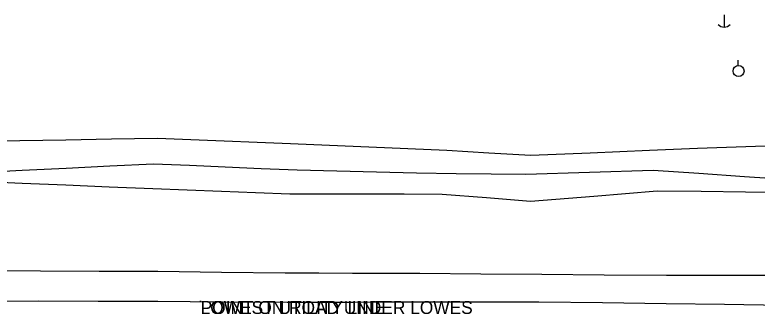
# Model space of a CAD drawing. Extents: x 1939239 to 1943096, y 531224 to 537447.
# Drawn here: x 1940013.5 to 1940300.4, y 534763.5 to 534879.2 of the extents above; entities that cross this region are included whole.
import ezdxf

# ---------------------------------------------------------------- set-up
doc = ezdxf.new("R2010")
doc.units = 0
for name, color, linetype in [('S_DITCHLINE', 7, 'Continuous'), ('S_EDGE_PAVEMENT', 7, 'Continuous'), ('S_ELECTRIC_UTILITIES_ANNOT', 7, 'Continuous'), ('S_MSC_PT_SYM', 7, 'Continuous'), ('S_PAVEMENT_CROWN', 7, 'Continuous'), ('S_SURVEY_TEXT_ANNOT', 7, 'Continuous'), ('S_UTILITY_POLE', 7, 'Continuous'), ('S_UTL_PT_SYM', 7, 'Continuous')]:
    doc.layers.add(name, color=color, linetype=linetype)

msp = doc.modelspace()

# ---------------------------------------------------------------- linework, layer by layer
at = {"layer": 'S_DITCHLINE'}
for points in [[(1940314.63, 534828.78), (1940295.99, 534828.12), (1940277.35, 534827.45), (1940258.7, 534826.78), (1940235.79, 534825.77), (1940212.88, 534824.76), (1940196.66, 534825.76), (1940180.44, 534826.76), (1940165.34, 534827.39), (1940150.24, 534828.03), (1940135.14, 534828.66), (1940120.04, 534829.3), (1940107.19, 534829.82), (1940094.33, 534830.34), (1940081.48, 534830.86), (1940068.62, 534831.38), (1940050.9, 534831.06), (1940033.18, 534830.75), (1940015.45, 534830.44), (1939997.73, 534830.12)], [(1940313.14, 534815.42), (1940295.47, 534816.61), (1940277.8, 534817.81), (1940260.13, 534819), (1940235.57, 534818.24), (1940211, 534817.49), (1940197.54, 534817.57), (1940184.07, 534817.66), (1940168.68, 534818.02), (1940153.3, 534818.39), (1940137.91, 534818.76), (1940122.53, 534819.13), (1940108.66, 534819.71), (1940094.8, 534820.3), (1940080.93, 534820.88), (1940067.06, 534821.47), (1940050.16, 534820.64), (1940033.26, 534819.81), (1940016.36, 534818.98), (1939999.46, 534818.15)], [(1940313, 534810.48), (1940295.89, 534810.66), (1940278.78, 534810.84), (1940261.66, 534811.02), (1940237.23, 534809.01), (1940212.79, 534807.01), (1940195.74, 534808.4), (1940178.69, 534809.79), (1940163.96, 534809.8), (1940149.23, 534809.8), (1940134.5, 534809.8), (1940119.78, 534809.8), (1940106.54, 534810.32), (1940093.3, 534810.84), (1940080.06, 534811.35), (1940066.82, 534811.87), (1940049.99, 534812.58), (1940033.16, 534813.3), (1940016.33, 534814.01), (1939999.5, 534814.73)]]:
    msp.add_lwpolyline(points, dxfattribs=at)
at = {"layer": 'S_EDGE_PAVEMENT'}
msp.add_lwpolyline([(1939852.77, 534782.14), (1939874.25, 534781.93), (1939896.9, 534781.77), (1939919.55, 534781.6), (1939942.13, 534781.22), (1939964.7, 534780.83), (1939979.38, 534780.67), (1939994.06, 534780.51), (1940008.74, 534780.35), (1940023.42, 534780.18), (1940046.09, 534780.11), (1940068.75, 534780.04), (1940093.37, 534779.74), (1940118, 534779.43), (1940130.99, 534779.4), (1940143.99, 534779.36), (1940156.99, 534779.33), (1940169.99, 534779.3), (1940193.57, 534779.1), (1940217.16, 534778.91), (1940241.23, 534778.7), (1940265.3, 534778.5), (1940288.18, 534778.5), (1940311.06, 534778.51)], dxfattribs=at)
at = {"layer": 'S_MSC_PT_SYM'}
msp.add_lwpolyline([(1940085.29, 534768.53), (1940085.29, 534768.58), (1940085.29, 534768.53), (1940085.24, 534768.53), (1940085.29, 534768.53), (1940085.29, 534768.48), (1940085.29, 534768.53), (1940085.34, 534768.53)], dxfattribs=at)
at = {"layer": 'S_PAVEMENT_CROWN'}
msp.add_lwpolyline([(1939852.31, 534771.21), (1939874.42, 534771.08), (1939896.28, 534770.35), (1939918.14, 534769.62), (1939939.65, 534769.35), (1939961.17, 534769.08), (1939985.43, 534768.78), (1940009.68, 534768.48), (1940022.61, 534768.64), (1940045.69, 534768.54), (1940068.77, 534768.44), (1940093.77, 534768.28), (1940118.76, 534768.12), (1940131.55, 534768.14), (1940144.34, 534768.16), (1940157.13, 534768.18), (1940169.93, 534768.2), (1940192.98, 534768.23), (1940216.04, 534768.26), (1940240.59, 534767.93), (1940265.13, 534767.61), (1940287.69, 534767.29), (1940310.25, 534766.96)], dxfattribs=at)
at = {"layer": 'S_UTILITY_POLE'}
for p, q in [((1940287.54, 534879.19), (1940287.54, 534874.47)), ((1940293.04, 534859.6), (1940293.04, 534861.7))]:
    msp.add_line(p, q, dxfattribs=at)
msp.add_circle((1940293.16, 534857.45), 2.13, dxfattribs=at)
msp.add_arc((1940287.6, 534877.89), 3.41, 226.3972, 313.6028, dxfattribs=at)
at = {"layer": 'S_UTL_PT_SYM'}
msp.add_lwpolyline([(1940085.29, 534768.53), (1940085.29, 534768.58), (1940085.29, 534768.53), (1940085.24, 534768.53), (1940085.29, 534768.53), (1940085.29, 534768.48), (1940085.29, 534768.53), (1940085.34, 534768.53)], dxfattribs=at)

# ---------------------------------------------------------------- texts
at = {"layer": 'S_ELECTRIC_UTILITIES_ANNOT'}
msp.add_text('LOWEST UTILITY LINE', height=5, dxfattribs=at).set_placement((1940085.29, 534763.53))
at = {"layer": 'S_SURVEY_TEXT_ANNOT'}
msp.add_text('POINT ON ROAD UNDER LOWES', height=5, dxfattribs=at).set_placement((1940085.29, 534763.53))

doc.saveas('drawing.dxf')
